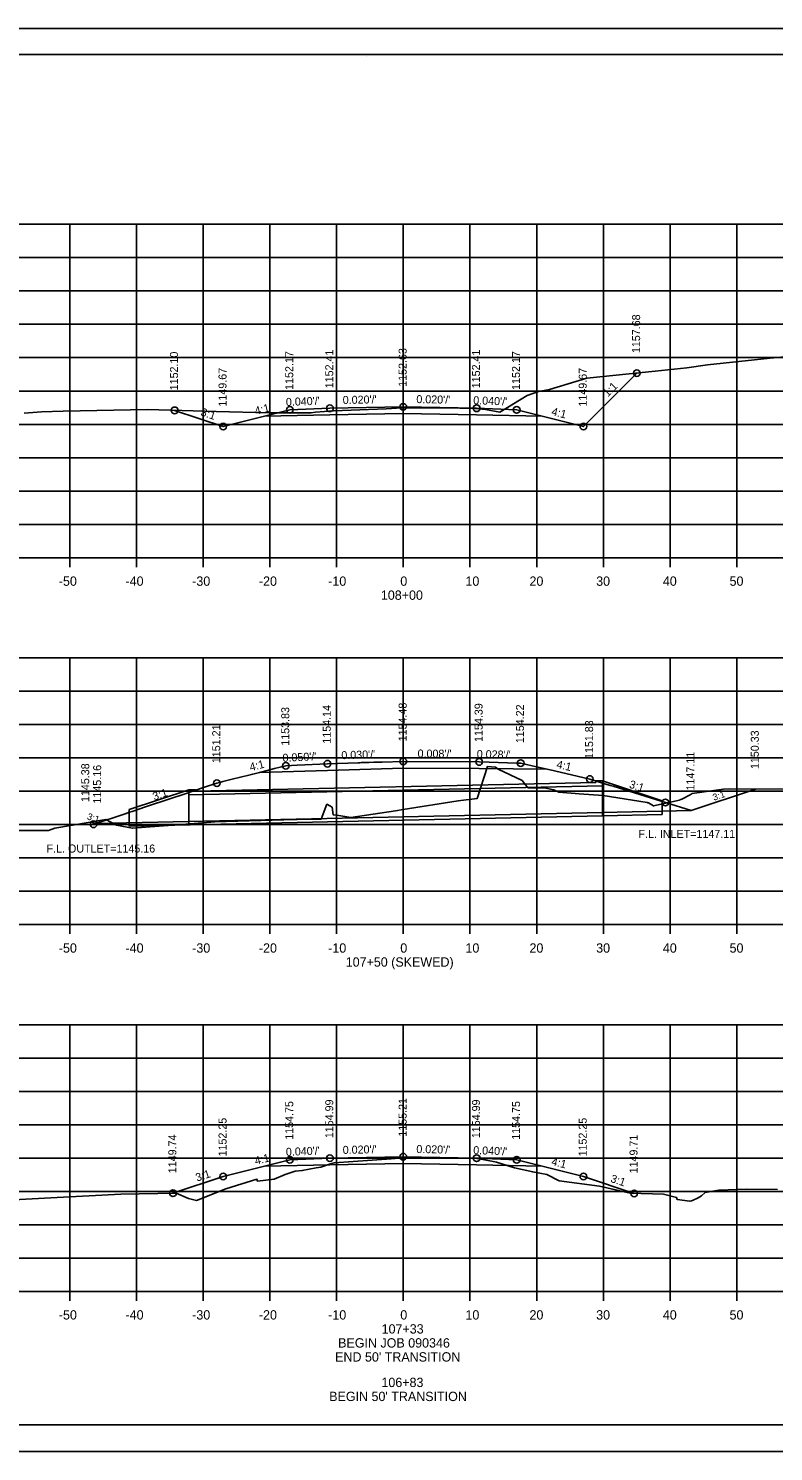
# Model space of a CAD drawing. Extents: x 1368971 to 1374497, y 378717 to 381839.
# Drawn here: x 1369497.6 to 1369609.3, y 380800.3 to 381013.6 of the extents above; entities that cross this region are included whole.
import ezdxf

# ---------------------------------------------------------------- set-up
doc = ezdxf.new("R2010")
doc.units = 0
for name, color, linetype in [('R_Alt Surface', 7, 'Continuous'), ('R_Axis', 7, 'Continuous'), ('R_Axis Annot', 7, 'Continuous'), ('R_Border', 7, 'Continuous'), ('R_Exist Surface', 7, 'Continuous'), ('R_Fin Surface', 7, 'Continuous'), ('R_Grid', 7, 'Continuous'), ('R_No Plot', 7, 'Continuous'), ('R_Water', 7, 'Continuous'), ('R_Water Annot', 7, 'Continuous'), ('R_Xsect Elev', 7, 'Continuous'), ('R_Xsect Slope', 7, 'Continuous')]:
    doc.layers.add(name, color=color, linetype=linetype)

msp = doc.modelspace()

# ---------------------------------------------------------------- linework, layer by layer
at = {"layer": 'R_Alt Surface'}
for points in [[(1369533.01, 380955.47), (1369542.83, 380955.67), (1369553.83, 380955.89), (1369564.83, 380955.67), (1369574.66, 380955.47)], [(1369532.27, 380902.08), (1369542.45, 380902.39), (1369553.83, 380902.74), (1369565.22, 380902.65), (1369575.4, 380902.56)], [(1369533.01, 380843.05), (1369542.83, 380843.25), (1369553.83, 380843.47), (1369564.83, 380843.25), (1369574.66, 380843.05)]]:
    msp.add_lwpolyline(points, dxfattribs=at)
at = {"layer": 'R_Axis'}
for p, q in [((1369413.83, 380934.26), (1369693.83, 380934.26)), ((1369503.83, 380932.86), (1369503.83, 380934.26)), ((1369513.83, 380932.86), (1369513.83, 380934.26)), ((1369523.83, 380932.86), (1369523.83, 380934.26)), ((1369533.83, 380932.86), (1369533.83, 380934.26)), ((1369543.83, 380932.86), (1369543.83, 380934.26)), ((1369553.83, 380932.86), (1369553.83, 380934.26)), ((1369563.83, 380932.86), (1369563.83, 380934.26)), ((1369573.83, 380932.86), (1369573.83, 380934.26)), ((1369583.83, 380932.86), (1369583.83, 380934.26)), ((1369593.83, 380932.86), (1369593.83, 380934.26)), ((1369603.83, 380932.86), (1369603.83, 380934.26)), ((1369413.83, 380879.26), (1369693.83, 380879.26)), ((1369503.83, 380877.86), (1369503.83, 380879.26)), ((1369513.83, 380877.86), (1369513.83, 380879.26)), ((1369523.83, 380877.86), (1369523.83, 380879.26)), ((1369533.83, 380877.86), (1369533.83, 380879.26)), ((1369543.83, 380877.86), (1369543.83, 380879.26)), ((1369553.83, 380877.86), (1369553.83, 380879.26)), ((1369563.83, 380877.86), (1369563.83, 380879.26)), ((1369573.83, 380877.86), (1369573.83, 380879.26)), ((1369583.83, 380877.86), (1369583.83, 380879.26)), ((1369593.83, 380877.86), (1369593.83, 380879.26)), ((1369603.83, 380877.86), (1369603.83, 380879.26)), ((1369413.83, 380824.26), (1369693.83, 380824.26)), ((1369503.83, 380822.86), (1369503.83, 380824.26)), ((1369513.83, 380822.86), (1369513.83, 380824.26)), ((1369523.83, 380822.86), (1369523.83, 380824.26)), ((1369533.83, 380822.86), (1369533.83, 380824.26)), ((1369543.83, 380822.86), (1369543.83, 380824.26)), ((1369553.83, 380822.86), (1369553.83, 380824.26)), ((1369563.83, 380822.86), (1369563.83, 380824.26)), ((1369573.83, 380822.86), (1369573.83, 380824.26)), ((1369583.83, 380822.86), (1369583.83, 380824.26)), ((1369593.83, 380822.86), (1369593.83, 380824.26)), ((1369603.83, 380822.86), (1369603.83, 380824.26))]:
    msp.add_line(p, q, dxfattribs=at)
at = {"layer": 'R_Border'}
for p, q in [((1369395.83, 381009.72), (1369712.01, 381009.72)), ((1369548.35, 381009.46), (1369548.35, 381009.46)), ((1369548.35, 381009.46), (1369548.35, 381009.46)), ((1369712.01, 380804.26), (1369395.83, 380804.26))]:
    msp.add_line(p, q, dxfattribs=at)
at = {"layer": 'R_Exist Surface'}
for points in [[(1369496.98, 380955.93), (1369499.56, 380956.12), (1369502.85, 380956.26), (1369515.48, 380956.48), (1369525.77, 380956.17), (1369533.71, 380955.98), (1369534.47, 380956.01), (1369540.03, 380956), (1369540.66, 380956.08), (1369543.36, 380956.31), (1369551.25, 380956.61), (1369553.6, 380956.73), (1369562.33, 380956.68), (1369564.62, 380956.66), (1369565.16, 380956.57), (1369566.18, 380956.5), (1369568.32, 380956.1), (1369572.4, 380958.59), (1369574.1, 380959.19), (1369575.75, 380959.51), (1369581.35, 380961.18), (1369591.6, 380962.22), (1369596.32, 380962.71), (1369599.42, 380963.16), (1369608.84, 380964.18), (1369623.73, 380965.59)], [(1369495.22, 380893.36), (1369500.63, 380893.38), (1369501.58, 380893.74), (1369509.23, 380895.01), (1369510.85, 380894.18), (1369513.21, 380893.72), (1369521.25, 380894.34), (1369525.57, 380894.65), (1369537.61, 380895.02), (1369537.71, 380895.03), (1369537.78, 380895.03), (1369537.93, 380895.03), (1369541.5, 380895.09), (1369542.38, 380897.31), (1369542.83, 380897.06), (1369543.18, 380896.86), (1369543.31, 380895.73), (1369543.86, 380895.67), (1369545.96, 380895.3), (1369552.65, 380896.3), (1369553.8, 380896.54), (1369562.06, 380897.83), (1369564.92, 380898.19), (1369566.47, 380902.97), (1369567.63, 380902.89), (1369568.03, 380902.55), (1369571.63, 380900.86), (1369572.51, 380899.79), (1369575.18, 380899.73), (1369576.38, 380899.48), (1369577.16, 380899.13), (1369580.19, 380898.88), (1369583.8, 380898.62), (1369590.39, 380897.55), (1369590.5, 380897.5), (1369590.61, 380897.5), (1369591.35, 380897.07), (1369595.23, 380897.94), (1369595.3, 380897.96), (1369595.61, 380898.09), (1369596.86, 380898.72), (1369597.13, 380898.91), (1369601.86, 380899.59), (1369602.75, 380899.62), (1369610.89, 380899.55)], [(1369484.15, 380837.42), (1369500.99, 380838.31), (1369511.46, 380838.85), (1369519.79, 380839), (1369521.64, 380838.23), (1369522.83, 380837.89), (1369527.2, 380839.67), (1369531.89, 380841.1), (1369531.95, 380840.83), (1369534.46, 380841.13), (1369536.12, 380841.8), (1369537.62, 380842.3), (1369538.67, 380842.39), (1369540.78, 380842.78), (1369541.45, 380842.89), (1369542.76, 380843.36), (1369543.45, 380843.56), (1369552.03, 380844.16), (1369553.85, 380844.3), (1369562.87, 380844.26), (1369564.54, 380844.27), (1369565.53, 380844.1), (1369567.82, 380843.66), (1369570.52, 380842.79), (1369573.25, 380842.2), (1369575.37, 380841.8), (1369577.22, 380840.84), (1369583.23, 380840.05), (1369587.85, 380838.99), (1369592.85, 380838.84), (1369594.81, 380838.37), (1369594.9, 380838.04), (1369596.81, 380837.83), (1369596.84, 380837.8), (1369597.02, 380837.85), (1369597.2, 380837.9), (1369598.04, 380838.31), (1369598.52, 380838.61), (1369599.08, 380839.09), (1369601.16, 380839.44), (1369605.34, 380839.59), (1369609.96, 380839.55)]]:
    msp.add_lwpolyline(points, dxfattribs=at)
at = {"layer": 'R_Fin Surface'}
for p, q in [((1369596.98, 380896.37), (1369606.63, 380899.58)), ((1369593.12, 380897.57), (1369596.98, 380896.37)), ((1369507.7, 380894.41), (1369506.99, 380894.64))]:
    msp.add_line(p, q, dxfattribs=at)
for points in [[(1369519.55, 380956.36), (1369526.83, 380953.93), (1369533.01, 380955.47), (1369536.83, 380956.43), (1369542.83, 380956.67), (1369553.83, 380956.89), (1369564.83, 380956.67), (1369570.83, 380956.43), (1369574.66, 380955.47), (1369580.83, 380953.93), (1369588.84, 380961.94)], [(1369507.7, 380894.41), (1369509.09, 380894.87), (1369510.32, 380895.29), (1369510.64, 380895.39), (1369512.13, 380895.89), (1369512.8, 380896.11), (1369513.17, 380896.24), (1369515.2, 380896.91), (1369518.96, 380898.16), (1369520.98, 380898.84), (1369524.02, 380899.85), (1369525.88, 380900.47), (1369526.45, 380900.61), (1369526.79, 380900.7), (1369528.17, 380901.05), (1369530.65, 380901.67), (1369531.26, 380901.83), (1369532.27, 380902.08), (1369533.41, 380902.37), (1369534.52, 380902.65), (1369536.23, 380903.08), (1369537.92, 380903.17), (1369542.45, 380903.39), (1369547.06, 380903.53), (1369547.33, 380903.54), (1369547.53, 380903.55), (1369547.67, 380903.55), (1369547.79, 380903.56), (1369548.68, 380903.58), (1369549.42, 380903.61), (1369550.65, 380903.64), (1369553.83, 380903.74), (1369565.22, 380903.65), (1369566.72, 380903.6), (1369570.82, 380903.49), (1369571.43, 380903.47), (1369573.15, 380903.08), (1369575.4, 380902.56), (1369576.5, 380902.31), (1369581.79, 380901.09), (1369584.85, 380900.14), (1369585.28, 380900), (1369592.47, 380897.77), (1369593.12, 380897.57)], [(1369519.3, 380839), (1369526.83, 380841.51), (1369533.01, 380843.05), (1369536.83, 380844.01), (1369542.83, 380844.25), (1369553.83, 380844.47), (1369564.83, 380844.25), (1369570.83, 380844.01), (1369574.66, 380843.05), (1369580.83, 380841.51), (1369588.45, 380838.97)]]:
    msp.add_lwpolyline(points, dxfattribs=at)
at = {"layer": 'R_Grid'}
for p, q in [((1369413.83, 380984.26), (1369693.83, 380984.26)), ((1369503.83, 380934.26), (1369503.83, 380984.26)), ((1369513.83, 380934.26), (1369513.83, 380984.26)), ((1369523.83, 380934.26), (1369523.83, 380984.26)), ((1369533.83, 380934.26), (1369533.83, 380984.26)), ((1369543.83, 380934.26), (1369543.83, 380984.26)), ((1369553.83, 380934.26), (1369553.83, 380984.26)), ((1369563.83, 380934.26), (1369563.83, 380984.26)), ((1369573.83, 380934.26), (1369573.83, 380984.26)), ((1369583.83, 380934.26), (1369583.83, 380984.26)), ((1369593.83, 380934.26), (1369593.83, 380984.26)), ((1369603.83, 380934.26), (1369603.83, 380984.26)), ((1369413.83, 380979.26), (1369693.83, 380979.26)), ((1369413.83, 380974.26), (1369693.83, 380974.26)), ((1369413.83, 380969.26), (1369693.83, 380969.26)), ((1369413.83, 380964.26), (1369693.83, 380964.26)), ((1369413.83, 380959.26), (1369693.83, 380959.26)), ((1369413.83, 380954.26), (1369693.83, 380954.26)), ((1369413.83, 380949.26), (1369693.83, 380949.26)), ((1369413.83, 380944.26), (1369693.83, 380944.26)), ((1369413.83, 380939.26), (1369693.83, 380939.26)), ((1369413.83, 380934.26), (1369693.83, 380934.26)), ((1369413.83, 380919.26), (1369693.83, 380919.26)), ((1369503.83, 380879.26), (1369503.83, 380919.26)), ((1369513.83, 380879.26), (1369513.83, 380919.26)), ((1369523.83, 380879.26), (1369523.83, 380919.26)), ((1369533.83, 380879.26), (1369533.83, 380919.26)), ((1369543.83, 380879.26), (1369543.83, 380919.26)), ((1369553.83, 380879.26), (1369553.83, 380919.26)), ((1369563.83, 380879.26), (1369563.83, 380919.26)), ((1369573.83, 380879.26), (1369573.83, 380919.26)), ((1369583.83, 380879.26), (1369583.83, 380919.26)), ((1369593.83, 380879.26), (1369593.83, 380919.26)), ((1369603.83, 380879.26), (1369603.83, 380919.26)), ((1369413.83, 380914.26), (1369693.83, 380914.26)), ((1369413.83, 380909.26), (1369693.83, 380909.26)), ((1369413.83, 380904.26), (1369693.83, 380904.26)), ((1369413.83, 380899.26), (1369693.83, 380899.26)), ((1369413.83, 380894.26), (1369693.83, 380894.26)), ((1369413.83, 380889.26), (1369693.83, 380889.26)), ((1369413.83, 380884.26), (1369693.83, 380884.26)), ((1369413.83, 380879.26), (1369693.83, 380879.26)), ((1369413.83, 380864.26), (1369693.83, 380864.26)), ((1369503.83, 380824.26), (1369503.83, 380864.26)), ((1369513.83, 380824.26), (1369513.83, 380864.26)), ((1369523.83, 380824.26), (1369523.83, 380864.26)), ((1369533.83, 380824.26), (1369533.83, 380864.26)), ((1369543.83, 380824.26), (1369543.83, 380864.26)), ((1369553.83, 380824.26), (1369553.83, 380864.26)), ((1369563.83, 380824.26), (1369563.83, 380864.26)), ((1369573.83, 380824.26), (1369573.83, 380864.26)), ((1369583.83, 380824.26), (1369583.83, 380864.26)), ((1369593.83, 380824.26), (1369593.83, 380864.26)), ((1369603.83, 380824.26), (1369603.83, 380864.26)), ((1369413.83, 380859.26), (1369693.83, 380859.26)), ((1369413.83, 380854.26), (1369693.83, 380854.26)), ((1369413.83, 380849.26), (1369693.83, 380849.26)), ((1369413.83, 380844.26), (1369693.83, 380844.26)), ((1369413.83, 380839.26), (1369693.83, 380839.26)), ((1369413.83, 380834.26), (1369693.83, 380834.26)), ((1369413.83, 380829.26), (1369693.83, 380829.26)), ((1369413.83, 380824.26), (1369693.83, 380824.26))]:
    msp.add_line(p, q, dxfattribs=at)
at = {"layer": 'R_No Plot'}
for p, q in [((1369383.43, 381013.61), (1369716.77, 381013.61)), ((1369383.43, 380800.28), (1369716.77, 380800.28))]:
    msp.add_line(p, q, dxfattribs=at)
for points in [[(1369383.43, 381013.61), (1369716.77, 381013.61), (1369716.77, 380800.27), (1369383.43, 380800.27)], [(1369629.75, 381009.72), (1369629.75, 380999.84), (1369665.49, 380999.84), (1369665.49, 380996.92), (1369688.69, 380996.92), (1369688.69, 380973.7), (1369712.01, 380973.7), (1369712.01, 380804.26), (1369395.83, 380804.26), (1369395.83, 381009.72)]]:
    msp.add_lwpolyline(points, close=True, dxfattribs=at)
for centre in [(1369588.84, 380961.94), (1369542.83, 380956.67), (1369553.83, 380956.89), (1369564.83, 380956.67), (1369519.55, 380956.36), (1369536.83, 380956.43), (1369570.83, 380956.43), (1369526.83, 380953.93), (1369580.83, 380953.93), (1369542.45, 380903.39), (1369553.83, 380903.74), (1369565.22, 380903.65), (1369571.43, 380903.47), (1369536.23, 380903.08), (1369581.79, 380901.09), (1369525.88, 380900.47), (1369593.12, 380897.57), (1369507.4, 380894.31), (1369536.83, 380844.01), (1369542.83, 380844.25), (1369553.83, 380844.47), (1369564.83, 380844.25), (1369570.83, 380844.01), (1369526.83, 380841.51), (1369580.83, 380841.51), (1369519.3, 380839), (1369588.45, 380838.97)]:
    msp.add_circle(centre, 0.5, dxfattribs=at)
at = {"layer": 'R_Water'}
for p, q in [((1369521.68, 380899.49), (1369512.74, 380896.51)), ((1369583.68, 380900.07), (1369521.68, 380898.73)), ((1369521.68, 380894.24), (1369521.68, 380899.49)), ((1369582.68, 380900.55), (1369522.68, 380899.25)), ((1369583.68, 380900.82), (1369583.68, 380895.57)), ((1369583.68, 380900.82), (1369592.62, 380897.84)), ((1369592.62, 380895.77), (1369592.62, 380897.84)), ((1369512.74, 380894.03), (1369512.74, 380896.51)), ((1369583.68, 380895.57), (1369512.74, 380894.04)), ((1369583.68, 380896.07), (1369521.68, 380894.73)), ((1369583.68, 380896.07), (1369596.98, 380896.37)), ((1369583.68, 380895.57), (1369592.62, 380895.77)), ((1369521.68, 380894.73), (1369507.7, 380894.41))]:
    msp.add_line(p, q, dxfattribs=at)
for points in [[(1369521.68, 380899.49), (1369522.68, 380899.49), (1369522.68, 380899.25)], [(1369583.68, 380900.82), (1369582.68, 380900.82), (1369582.68, 380900.55)]]:
    msp.add_lwpolyline(points, dxfattribs=at)

# ---------------------------------------------------------------- texts
at = {"layer": 'R_Axis Annot'}
for s, p in [('-50', (1369502.18, 380930.06)), ('-40', (1369512.18, 380930.06)), ('-30', (1369522.18, 380930.06)), ('-20', (1369532.18, 380930.06)), ('-10', (1369542.57, 380930.06)), ('0', (1369553.38, 380930.06)), ('10', (1369563.15, 380930.06)), ('20', (1369572.75, 380930.06)), ('30', (1369582.75, 380930.06)), ('40', (1369592.75, 380930.06)), ('50', (1369602.75, 380930.06)), ('108+00', (1369550.47, 380927.96)), ('-50', (1369502.18, 380875.06)), ('-40', (1369512.18, 380875.06)), ('-30', (1369522.18, 380875.06)), ('-20', (1369532.18, 380875.06)), ('-10', (1369542.57, 380875.06)), ('0', (1369553.38, 380875.06)), ('10', (1369563.15, 380875.06)), ('20', (1369572.75, 380875.06)), ('30', (1369582.75, 380875.06)), ('40', (1369592.75, 380875.06)), ('50', (1369602.75, 380875.06)), ('107+50 (SKEWED)', (1369545.2, 380872.96)), ('-50', (1369502.18, 380820.06)), ('-40', (1369512.18, 380820.06)), ('-30', (1369522.18, 380820.06)), ('-20', (1369532.18, 380820.06)), ('-10', (1369542.57, 380820.06)), ('0', (1369553.38, 380820.06)), ('10', (1369563.15, 380820.06)), ('20', (1369572.75, 380820.06)), ('30', (1369582.75, 380820.06)), ('40', (1369592.75, 380820.06)), ('50', (1369602.75, 380820.06)), ('107+33', (1369550.58, 380817.96)), ('107+33', (1369550.58, 380817.96)), ('BEGIN JOB 090346', (1369544.06, 380815.86)), ("END 50' TRANSITION", (1369543.61, 380813.76)), ('106+83', (1369550.55, 380809.94)), ("BEGIN 50' TRANSITION", (1369542.72, 380807.84))]:
    msp.add_text(s, height=1.4, dxfattribs=at).set_placement(p)
at = {"layer": 'R_Water Annot'}
for s, p in [('F.L. INLET=1147.11', (1369589.09, 380892.27)), ('F.L. OUTLET=1145.16', (1369500.35, 380890.07))]:
    msp.add_text(s, height=1.2, dxfattribs=at).set_placement(p)
at = {"layer": 'R_Xsect Elev'}
for s, p in [('1157.68', (1369589.34, 380964.94)), ('1152.63', (1369554.33, 380959.89)), ('1152.10', (1369520.05, 380959.36)), ('1152.17', (1369537.33, 380959.43)), ('1152.41', (1369543.33, 380959.67)), ('1152.41', (1369565.33, 380959.67)), ('1152.17', (1369571.33, 380959.43)), ('1149.67', (1369527.33, 380956.93)), ('1149.67', (1369581.33, 380956.93)), ('1154.48', (1369554.33, 380906.74)), ('1154.39', (1369565.72, 380906.65)), ('1154.22', (1369571.93, 380906.47)), ('1153.83', (1369536.73, 380906.08)), ('1154.14', (1369542.95, 380906.39)), ('1151.21', (1369526.38, 380903.47)), ('1151.83', (1369582.29, 380904.09)), ('1150.33', (1369607.13, 380902.58)), ('1147.11', (1369597.48, 380899.37)), ('1145.38', (1369506.74, 380897.64)), ('1145.16', (1369508.53, 380897.41)), ('1154.75', (1369537.33, 380847.01)), ('1154.99', (1369543.33, 380847.25)), ('1155.21', (1369554.33, 380847.47)), ('1154.99', (1369565.33, 380847.25)), ('1154.75', (1369571.33, 380847.01)), ('1152.25', (1369527.33, 380844.51)), ('1152.25', (1369581.33, 380844.51)), ('1149.74', (1369519.8, 380842)), ('1149.71', (1369588.95, 380841.97))]:
    msp.add_text(s, height=1.2, rotation=90, dxfattribs=at).set_placement(p)
at = {"layer": 'R_Xsect Slope'}
for s, height, rotation, p in [('1:1', 1.2, 45, (1369584.49, 380958.29)), ('4:1', 1.2, 14.0362, (1369531.71, 380955.67)), ("0.040'/'", 1.2, 2.2906, (1369536.25, 380957.01)), ("0.020'/'", 1.2, 1.1458, (1369544.76, 380957.31)), ("0.020'/'", 1.2, 358.8542, (1369555.78, 380957.45)), ("0.040'/'", 1.2, 357.7094, (1369564.3, 380957.29)), ('3:1', 1.2, 341.5651, (1369523.35, 380955.62)), ('4:1', 1.2, 345.9638, (1369575.96, 380955.67)), ('4:1', 1.2, 14.1751, (1369530.94, 380902.26)), ("0.050'/'", 1.2, 2.8471, (1369535.75, 380903.66)), ("0.030'/'", 1.2, 1.742, (1369544.56, 380904.06)), ("0.008'/'", 1.2, 359.5288, (1369555.97, 380904.32)), ("0.028'/'", 1.2, 358.4223, (1369564.83, 380904.26)), ('4:1', 1.2, 347.0262, (1369576.72, 380902.77)), ('3:1', 1.2, 18.4213, (1369516.48, 380897.87)), ('3:1', 1.2, 342.7305, (1369587.6, 380899.81)), ('3:1', 1, 18.4213, (1369600.41, 380897.83)), ('3:1', 1, 342.7305, (1369506.34, 380895.06)), ("0.040'/'", 1.2, 2.2906, (1369536.25, 380844.59)), ("0.020'/'", 1.2, 1.1458, (1369544.76, 380844.89)), ("0.020'/'", 1.2, 358.8542, (1369555.78, 380845.03)), ("0.040'/'", 1.2, 357.7094, (1369564.3, 380844.87)), ('4:1', 1.2, 14.0362, (1369531.71, 380843.24)), ('4:1', 1.2, 345.9638, (1369575.96, 380843.24)), ('3:1', 1.2, 18.4349, (1369522.91, 380840.73)), ('3:1', 1.2, 341.5651, (1369584.8, 380840.71))]:
    msp.add_text(s, height=height, rotation=rotation, dxfattribs=at).set_placement(p)

doc.saveas('drawing.dxf')
